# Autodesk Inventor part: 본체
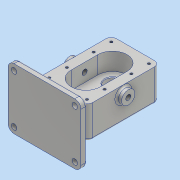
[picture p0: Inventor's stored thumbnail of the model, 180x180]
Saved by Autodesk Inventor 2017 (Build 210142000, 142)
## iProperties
Part Number: 본체
Material: 알루미늄 6061
Document SubType Name: Modeling
Designer: MRC
Density: 2.7 g/cm^3
Appearance: 알루미늄 - 평지
Mass: 1472.66 g
Surface Area: 819.597 cm^2
Volume: 545.428 cm^3
Author: MRC
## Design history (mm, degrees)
sketch "스케치1"
  geometry: L1 (-40, -60)-(40, -60); L2 (40, -60)-(40, 60); L3 (40, 60)-(-40, 60); L4 (-40, 60)-(-40, -60); L5 (-40, -60)-(40, 60); L6 (40, -60)-(-40, 60); 1 further point
  constraints: 12 end point, 2 midpoint, 2 parallel, 1 horizontal, 1 perpendicular
  dimensions: "d0" = 80 distance of L2.end L3.end; "d1" = 120 distance of L1.end L2.end
extrude "돌출1" new body sketch "스케치1" stored distance "d2" = 53; taper "d3" = 0 deg
sketch "스케치2"
  geometry: L1 (24, -22)-(24, 22); L2 (-24, -22)-(-24, 22); A1 r 24 centre (0, -22) between (-24, -22) and (24, -22); A2 r 24 centre (0, 22) between (24, 22) and (-24, 22); 1 further point
  constraints: 4 end point, 4 point on circle, 4 tangent, 2 centre point, 2 vertical alignment
  dimensions: "d7" = 22 distance of point (0, 0) A2.centre; "d8" = 48 diameter of A1; "d9" = 44 distance of A2.centre A1.centre; "d10" = 24 distance from line of L1 point (0, 0)
extrude "돌출2" cut sketch "스케치2" distance "d11" = 29; taper "d12" = 0 deg
sketch "스케치3"
  geometry: A1 r 24 centre (0, 22) between (24, 22) and (-24, 22) reference; 2 further points
  constraints: 1 coincident
hole "구멍1" sketch "스케치3" at (0, 22) diameter "d13" = 17; stored, may be unused: countersink angle "d17" = 90 deg, drill point angle "d19" = 0 deg; dims "d14" = 6, "d15" = 25, "d16" = 15, "d18" = 20
sketch "스케치4"
  geometry: C1 r 19 at (0, 22); 1 further point
  constraints: 1 centre point, 1 vertical alignment
  dimensions: "d20" = 38 diameter of C1; "d21" = 22 distance of point (0, 0) C1.centre
extrude "돌출3" join sketch "스케치4" distance "d22" = 17; taper "d23" = 0 deg
sketch "스케치5"
  geometry: C1 r 19 at (0, 0) reference; 2 further points
  constraints: 1 coincident
hole "구멍2" sketch "스케치5" at (0, 0) diameter "d24" = 17; stored, may be unused: countersink angle "d28" = 90 deg, drill point angle "d30" = 118 deg; dims "d25" = 6, "d26" = 28, "d27" = 7.3, "d29" = 20
sketch "스케치6"
  geometry: C1 r 12.5 at (0, -22); A1 r 24 centre (0, -22) between (-24, -22) and (24, -22) reference; 1 further point
  constraints: 1 centre point, 1 coincident
  dimensions: "d31" = 25 diameter of C1
extrude "돌출4" cut sketch "스케치6" distance "d32" = 15; taper "d33" = 0 deg
sketch "스케치7"
  geometry: L1 (0, 0)-(0, 120) reference; C1 r 11 at (14, 60); 1 further point
  constraints: 1 centre point
  dimensions: "d34" = 14 distance from line of C1.centre L1; "d35" = 22 diameter of C1
extrude "돌출5" join sketch "스케치7" distance "d36" = 8; taper "d37" = 0 deg
sketch "스케치8"
  geometry: C1 r 11 at (0, 0) reference; 2 further points
  constraints: 1 coincident
hole "구멍3" sketch "스케치8" at (0, 0) diameter "d38" = 8.376; stored, may be unused: countersink angle "d42" = 90 deg, drill point angle "d44" = 118 deg; dims "d39" = 40, "d40" = 28, "d41" = 7.3, "d43" = 41.05
node "작업 평면1"
sketch "스케치9"
  geometry: L1 (60, 56.5)-(-60, 56.5); L2 (-60, 56.5)-(-60, -43.5); L3 (-60, -43.5)-(60, -43.5); L4 (60, -43.5)-(60, 56.5); L5 (-19, -43.5)-(19, -43.5) reference; 1 further point
  constraints: 8 end point, 2 parallel, 1 horizontal, 1 perpendicular
  dimensions: "d46" = 0 distance between parallel lines of L5 L3; "d47" = 100 distance of L3.end L1.start; "d48" = 60 distance from line of L4 point (0, 0); "d49" = 60 distance from line of L2 point (0, 0)
extrude "돌출6" join sketch "스케치9" distance "d50" = 10; taper "d51" = 0 deg
sketch "스케치10"
  geometry: 2 further points
  dimensions: "d52" = 31 horizontal distance of point (0, 0) point (-31, 51); "d53" = 51 vertical distance of point (-31, 51) point (0, 0)
hole "구멍4" sketch "스케치10" at (-31, 51) diameter "d54" = 4.134; stored, may be unused: countersink angle "d58" = 90 deg, drill point angle "d60" = 118 deg; dims "d55" = 10, "d56" = 28, "d57" = 7.3, "d59" = 12
fillet "모깎기1" dims "d64" = 9
fillet "모깎기2" dims "d65" = 9
fillet "모깎기3" dims "d66" = 9
sketch "스케치11"
  geometry: L1 (60, 43.5)-(-60, 43.5) reference; L2 (-24, -26.5)-(24, -26.5); L3 (24, -26.5)-(24, 26.5); L4 (24, 26.5)-(-24, 26.5); L5 (-24, 26.5)-(-24, -26.5); 1 further point
  constraints: 8 end point, 2 parallel, 1 horizontal, 1 perpendicular
  dimensions: "d67" = 17 distance between parallel lines of L4 L1; "d69" = 24 distance from line of L3 point (0, 0); "d70" = 24 distance from line of L5 point (0, 0); "d71" = 53 distance between parallel lines of L4 L2
extrude "돌출7" join sketch "스케치11" distance "d72" = 20; taper "d73" = 0 deg
sketch "스케치13"
  geometry: L1 (53, 0)-(0, 0) reference; L2 (0, 20)-(53, 20) reference; L3 (0, 0)-(0, 20) reference; L4 (0, 0)-(11.547, 20); L5 (53, 0)-(42.082, 18.911); 1 further point
  constraints: 4 end point, 1 point on line
  dimensions: "d74" = 60 deg angle of L1 L4; "d75" = 60 deg angle of L1 L5
extrude "돌출8" cut sketch "스케치13" distance "d76" = 214.75; taper "d77" = 0 deg
chamfer "모따기1" distance "d78" = 1; stored, may be unused: second distance "d79" = 2, angle "d80" = 45 deg
chamfer "모따기2" distance "d81" = 1; stored, may be unused: second distance "d82" = 2, angle "d83" = 45 deg
chamfer "모따기3" distance "d84" = 0.7; stored, may be unused: second distance "d85" = 2, angle "d86" = 30 deg
fillet "모깎기4" dims "d87" = 0.5
fillet "모깎기5" dims "d88" = 3
fillet "모깎기6" dims "d89" = 3
fillet "모깎기7" dims "d90" = 3
fillet "모깎기8" dims "d91" = 3
fillet "모깎기9" dims "d92" = 3
fillet "모깎기10" dims "d93" = 3
sketch "스케치14"
  geometry: L1 (60, -56.5)-(60, 43.5) reference; L2 (60, 43.5)-(-60, 43.5) reference; C1 r 4.5 at (50, 33.5); 2 further points
  constraints: 1 centre point, 1 coincident
  dimensions: "d94" = 10 distance from line of point (50, 33.5) L2; "d95" = 10 distance from line of L1 point (50, 33.5); "d96" = 9 diameter of C1
extrude "돌출9" cut sketch "스케치14" distance "d97" = 214.75; taper "d98" = 0 deg
fillet "모깎기11" dims "d99" = 10
fillet "모깎기12" dims "d100" = 10
fillet "모깎기13" dims "d104" = 3
sketch "스케치15"
  geometry: L1 (-50, -56.5)-(50, -56.5) reference; L2 (-60, 33.5)-(-60, -46.5) reference; 2 further points
  constraints: 1 other
  dimensions: "d105" = 10 distance from line of point (0, -46.5) L1; "d106" = 60 distance from line of point (0, -46.5) L2
feature "엠보싱1" sketch "스케치15" dims "d11" = 29, "d16" = 15, "d74" = 60 deg, "d82" = 2, "d88" = 3, "d96" = 9, "d107" = 0.5, "d108" = 0
node "솔리드1"
mirror "미러1"
mirror "미러2"
pattern_linear "직사각형 패턴1" dims "d63" = 29
mirror "미러3"
mirror "미러4"
mirror "미러5"
pattern_linear "직사각형 패턴2" dims "d103" = 80
other parameters: "d6" = 48
